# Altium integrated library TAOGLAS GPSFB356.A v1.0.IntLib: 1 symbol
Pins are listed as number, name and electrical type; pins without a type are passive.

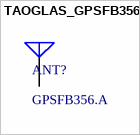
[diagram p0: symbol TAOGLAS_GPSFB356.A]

## TAOGLAS_GPSFB356.A
designator ANT?, comment GPSFB356.A
Multiband GNSS Single Feed 35 x 35 x 6mm Stacked Patch With GPS L1 / L2, GLONASS G1 and BeiDou B1; ComponentLibStatus: Created; MFG: Taoglas; Temp_High: +85C; Temp_Low: -40C
pins: 1 RF FEED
